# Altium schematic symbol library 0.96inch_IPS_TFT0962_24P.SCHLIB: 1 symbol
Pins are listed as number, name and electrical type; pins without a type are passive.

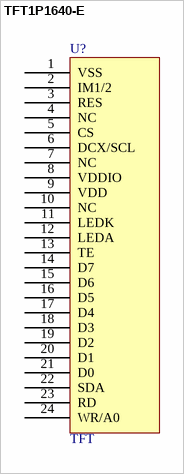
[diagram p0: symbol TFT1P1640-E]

## TFT1P1640-E
designator U?, comment TFT
footprint TFT1P1640-E_BACK
pins: 1 VSS, 2 IM1/2, 3 RES, 4 NC, 5 CS, 6 DCX/SCL, 7 NC, 8 VDDIO, 9 VDD, 10 NC, 11 LEDK, 12 LEDA, 13 TE, 14 D7, 15 D6, 16 D5, 17 D4, 18 D3, 19 D2, 20 D1, 21 D0, 22 SDA, 23 RD, 24 WR/A0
